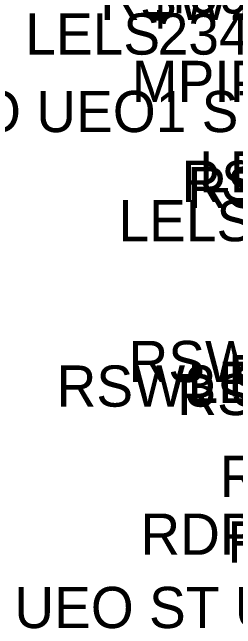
# Model space of a CAD drawing. Extents: x 1040177 to 1042343, y 1125540 to 1129143.
# Drawn here: x 1041507.4 to 1041561.6, y 1125700 to 1125849.5 of the extents above; entities that cross this region are included whole.
import ezdxf

# ---------------------------------------------------------------- set-up
doc = ezdxf.new("R2010")
doc.units = 0
for name, color, linetype in [('CDEFAULT', 7, 'Continuous'), ('COCOD', 7, 'Continuous'), ('COELE', 7, 'Continuous'), ('COPNT', 7, 'Continuous'), ('LELS', 7, 'Continuous')]:
    doc.layers.add(name, color=color, linetype=linetype)

msp = doc.modelspace()

# ---------------------------------------------------------------- linework, layer by layer
at = {"layer": 'LELS'}
for points in [[(1041542.67, 1125850.05), (1041542.67, 1125849.26)], [(1041541.89, 1125849.26), (1041542.67, 1125849.26)], [(1041542.67, 1125849.26), (1041543.46, 1125849.26)], [(1041542.67, 1125849.26), (1041542.67, 1125848.47)]]:
    msp.add_lwpolyline(points, dxfattribs=at)

# ---------------------------------------------------------------- texts
at = {"layer": 'CDEFAULT'}
for height, p in [(10, (1041539.41, 1125844.26)), (0.0781, (1041542.65, 1125849.22))]:
    msp.add_text('+', height=height, dxfattribs=at).set_placement(p)
at = {"layer": 'COCOD'}
for s, height, p in [('RSW1', 10, (1041528.75, 1125847.63)), ('LELS', 10, (1041510.55, 1125839.26)), ('LELS', 0.0781, (1041542.48, 1125849.18)), ('MPIP', 10, (1041536.38, 1125827.75)), ('UPL UEO UEO1 ST', 10, (1041450.8, 1125820.46)), ('LELB1', 10, (1041552.72, 1125805.8)), ('RSW2', 10, (1041548.42, 1125803.52)), ('RSW1', 10, (1041549.84, 1125802.02)), ('LELS', 10, (1041533.16, 1125793.97)), ('RSW3 ST', 10, (1041535.59, 1125759.79)), ('RDP1 ST', 10, (1041559.8, 1125756.35)), ('LELB1 ST', 10, (1041549.94, 1125754.73)), ('RSW3 ST', 10, (1041518.14, 1125753.83)), ('RSW3', 10, (1041547.44, 1125751.78)), ('RDP1 ST', 10, (1041557.76, 1125731.92)), ('RDP1 ST', 10, (1041538.47, 1125717.88)), ('RSW2 ST', 10, (1041559.61, 1125715.97)), ('UP UEO ST UEO1 ST', 10, (1041485.6, 1125700.1))]:
    msp.add_text(s, height=height, dxfattribs=at).set_placement(p)
at = {"layer": 'COELE'}
for height in [10, 0.0781]:
    msp.add_text('409.326', height=height, dxfattribs=at).set_placement((1041542.67, 1125849.26))
at = {"layer": 'COPNT'}
for s, height, p in [('2340', 10, (1041560.17, 1125847.63)), ('2341', 10, (1041542.67, 1125839.26)), ('2341', 0.0781, (1041542.67, 1125849.18))]:
    msp.add_text(s, height=height, dxfattribs=at).set_placement(p)

doc.saveas('drawing.dxf')
